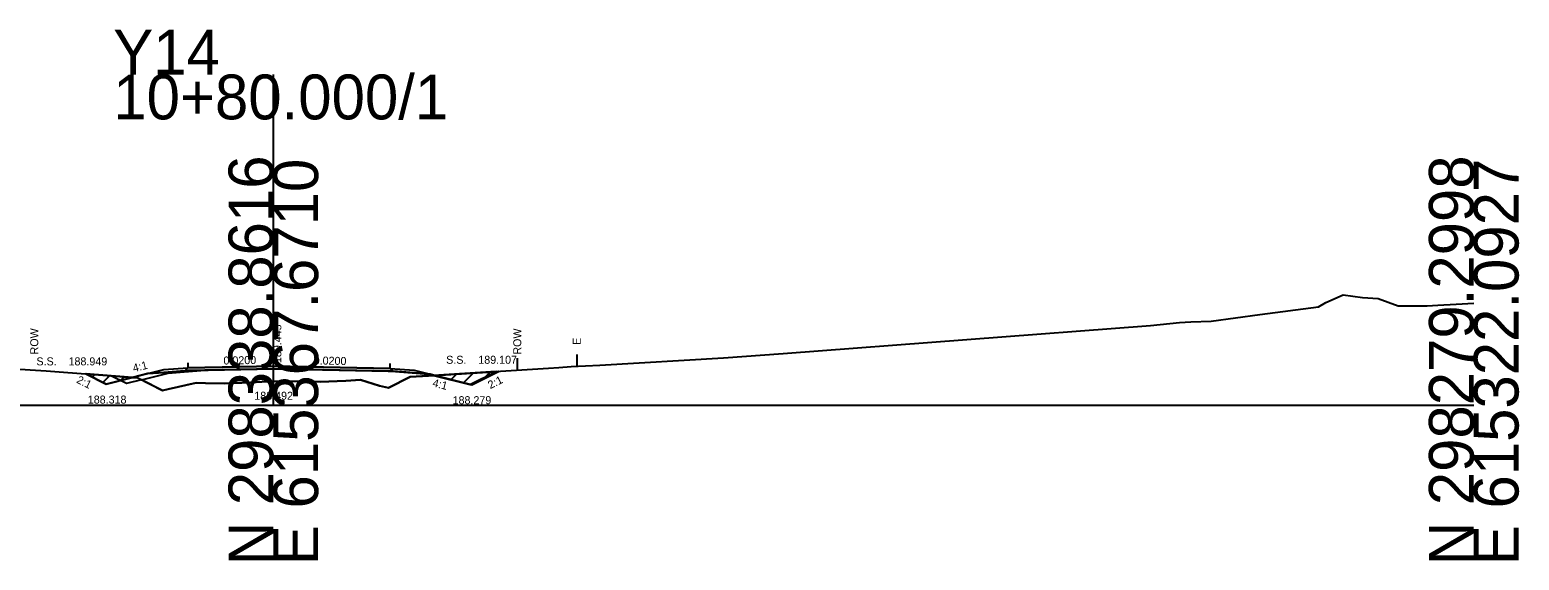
# Model space of a CAD drawing. Extents: x 517327 to 517505, y 114839 to 117370.
# Drawn here: x 517412.1 to 517505.2, y 116838.7 to 116871.8 of the extents above; entities that cross this region are included whole.
import ezdxf

# ---------------------------------------------------------------- set-up
doc = ezdxf.new("R2010")
doc.units = 0
for name, color, linetype in [('Exist XS Ground Line', 7, 'Continuous'), ('Old_Level_60', 7, 'Continuous'), ('Old_Level_63', 7, 'Continuous'), ('Prop XS Dump Level', 7, 'Continuous'), ('Prop XS Earthwork Shape', 7, 'Continuous'), ('Prop XS Elevation Labels', 7, 'Continuous'), ('Prop XS EOT Tick Mark', 7, 'Continuous'), ('Prop XS Exc Vertical Line 1', 7, 'Continuous'), ('Prop XS Exc Vertical Line 2', 7, 'Continuous'), ('Prop XS Finish Grade', 7, 'Continuous'), ('Prop XS Finish Grade Earthwork', 7, 'Continuous'), ('Prop XS Finish Grade Pavement', 7, 'Continuous'), ('Prop XS Hydro Elevations', 7, 'Continuous'), ('Prop XS Label Text', 7, 'Continuous'), ('Prop XS Pvmt Edge Slope', 7, 'Continuous'), ('Prop XS SE Text', 7, 'Continuous'), ('Prop XS Side Slope Text', 7, 'Continuous'), ('Prop XS Subgrade Earthwork', 7, 'Continuous'), ('Prop XS Suitable Common Exc Shape', 7, 'Continuous'), ('Scratch_Level_0', 7, 'Continuous')]:
    doc.layers.add(name, color=color, linetype=linetype)

msp = doc.modelspace()

# ---------------------------------------------------------------- linework, layer by layer
at = {"layer": 'Exist XS Ground Line'}
for p, q in [((517493.126, 116854.787), (517494.205, 116855.252)), ((517494.205, 116855.252), (517495.412, 116855.101)), ((517495.412, 116855.101), (517496.389, 116855.03)), ((517489.005, 116854.036), (517492.667, 116854.505)), ((517492.667, 116854.505), (517493.126, 116854.787)), ((517496.389, 116855.03), (517497.637, 116854.574)), ((517497.637, 116854.574), (517498.943, 116854.574)), ((517498.943, 116854.574), (517499.447, 116854.57)), ((517499.447, 116854.57), (517500.12, 116854.617)), ((517500.12, 116854.617), (517501.258, 116854.685)), ((517501.258, 116854.685), (517502.365, 116854.733)), ((517459.215, 116851.596), (517482.178, 116853.344)), ((517482.178, 116853.344), (517483.971, 116853.54)), ((517483.971, 116853.54), (517484.685, 116853.577)), ((517484.685, 116853.577), (517485.958, 116853.607)), ((517485.958, 116853.607), (517489.005, 116854.036)), ((517447.758, 116850.864), (517455.489, 116851.33)), ((517455.489, 116851.33), (517459.215, 116851.596)), ((517410.197, 116850.697), (517412.507, 116850.547)), ((517412.507, 116850.547), (517413.166, 116850.504)), ((517413.166, 116850.504), (517418.89, 116850.066)), ((517435.908, 116850.125), (517444.548, 116850.668)), ((517444.548, 116850.668), (517445.211, 116850.711)), ((517445.211, 116850.711), (517445.981, 116850.771)), ((517445.981, 116850.771), (517447.758, 116850.864)), ((517418.89, 116850.066), (517420.443, 116849.276)), ((517420.794, 116849.354), (517422.538, 116849.759)), ((517422.538, 116849.759), (517423.121, 116849.733)), ((517423.121, 116849.733), (517424.311, 116849.71)), ((517424.311, 116849.71), (517425.937, 116849.789)), ((517425.937, 116849.789), (517427.356, 116849.857)), ((517427.356, 116849.857), (517429.005, 116849.834)), ((517429.005, 116849.834), (517430.3, 116849.816)), ((517430.3, 116849.816), (517431.904, 116849.889)), ((517431.904, 116849.889), (517432.805, 116849.945)), ((517432.805, 116849.945), (517433.993, 116849.582)), ((517433.993, 116849.582), (517434.567, 116849.444)), ((517434.567, 116849.444), (517435.908, 116850.125)), ((517420.443, 116849.276), (517420.794, 116849.354))]:
    msp.add_line(p, q, dxfattribs=at)
at = {"layer": 'Old_Level_63'}
for p, q in [((517427.365, 116848.365), (517427.365, 116869.027)), ((517352.365, 116848.365), (517427.365, 116848.365)), ((517427.365, 116848.365), (517502.365, 116848.365))]:
    msp.add_line(p, q, dxfattribs=at)
at = {"layer": 'Prop XS Dump Level'}
for p, q in [((517422.019, 116850.703), (517427.365, 116850.81)), ((517427.365, 116850.81), (517434.67, 116850.664))]:
    msp.add_line(p, q, dxfattribs=at)
at = {"layer": 'Prop XS Earthwork Shape'}
for points in [[(517434.67, 116850.484), (517427.365, 116850.63), (517422.019, 116850.523), (517421.835, 116850.519), (517420.519, 116850.414), (517419.525, 116850.334), (517418.555, 116850.092), (517418.89, 116850.066), (517420.443, 116849.276), (517420.794, 116849.354), (517422.538, 116849.759), (517423.121, 116849.733), (517424.311, 116849.71), (517425.937, 116849.789), (517427.356, 116849.857), (517429.005, 116849.834), (517430.3, 116849.816), (517431.904, 116849.889), (517432.805, 116849.945), (517433.993, 116849.582), (517434.567, 116849.444), (517435.908, 116850.125), (517437.456, 116850.222), (517437.164, 116850.295), (517436.17, 116850.375), (517434.853, 116850.48)], [(517437.456, 116850.222), (517439.77, 116849.644), (517441.426, 116850.472)], [(517415.658, 116850.314), (517416.919, 116849.683), (517418.555, 116850.092)]]:
    msp.add_lwpolyline(points, close=True, dxfattribs=at)
at = {"layer": 'Prop XS EOT Tick Mark'}
for p, q in [((517422.019, 116851.008), (517422.019, 116850.703)), ((517434.67, 116850.664), (517434.67, 116850.969))]:
    msp.add_line(p, q, dxfattribs=at)
at = {"layer": 'Prop XS Exc Vertical Line 1'}
msp.add_line((517446.324, 116851.539), (517446.324, 116850.789), dxfattribs=at)
at = {"layer": 'Prop XS Exc Vertical Line 2'}
msp.add_line((517442.605, 116851.296), (517442.605, 116850.546), dxfattribs=at)
at = {"layer": 'Prop XS Finish Grade'}
for p, q in [((517419.525, 116850.334), (517420.519, 116850.583)), ((517420.519, 116850.583), (517422.019, 116850.703)), ((517434.67, 116850.664), (517436.17, 116850.544)), ((517436.17, 116850.544), (517437.164, 116850.295))]:
    msp.add_line(p, q, dxfattribs=at)
at = {"layer": 'Prop XS Finish Grade Earthwork'}
for p, q in [((517439.77, 116849.644), (517441.426, 116850.472)), ((517415.658, 116850.314), (517416.919, 116849.683)), ((517416.919, 116849.683), (517419.525, 116850.334)), ((517437.164, 116850.295), (517439.77, 116849.644))]:
    msp.add_line(p, q, dxfattribs=at)
at = {"layer": 'Prop XS Finish Grade Pavement'}
for p, q in [((517427.365, 116850.81), (517422.019, 116850.703)), ((517434.67, 116850.664), (517427.365, 116850.81))]:
    msp.add_line(p, q, dxfattribs=at)
at = {"layer": 'Prop XS Pvmt Edge Slope'}
for p, q in [((517421.835, 116850.519), (517422.019, 116850.703)), ((517434.67, 116850.664), (517434.853, 116850.48))]:
    msp.add_line(p, q, dxfattribs=at)
at = {"layer": 'Prop XS Subgrade Earthwork'}
for p, q in [((517419.525, 116850.334), (517420.519, 116850.414)), ((517420.519, 116850.414), (517421.835, 116850.519)), ((517421.835, 116850.519), (517422.019, 116850.523)), ((517427.365, 116850.63), (517422.019, 116850.523)), ((517434.67, 116850.484), (517427.365, 116850.63)), ((517434.67, 116850.484), (517434.853, 116850.48)), ((517434.853, 116850.48), (517436.17, 116850.375)), ((517436.17, 116850.375), (517437.164, 116850.295))]:
    msp.add_line(p, q, dxfattribs=at)
at = {"layer": 'Prop XS Suitable Common Exc Shape'}
for points in [[(517437.038, 116850.298), (517437.364, 116850.216), (517435.908, 116850.125), (517434.567, 116849.444), (517433.993, 116849.582), (517432.805, 116849.945), (517431.904, 116849.889), (517430.3, 116849.816), (517429.005, 116849.834), (517427.356, 116849.857), (517425.937, 116849.789), (517424.311, 116849.71), (517423.121, 116849.733), (517422.538, 116849.759), (517420.794, 116849.354), (517420.443, 116849.276), (517419.13, 116849.944), (517420.792, 116850.36), (517421.786, 116850.439), (517423.102, 116850.545), (517423.286, 116850.548), (517427.365, 116850.63), (517434.544, 116850.486), (517434.727, 116850.483), (517436.044, 116850.377)], [(517439.644, 116849.646), (517441.276, 116850.463), (517437.364, 116850.216)], [(517418.89, 116850.066), (517419.13, 116849.944), (517418.186, 116849.708), (517417.213, 116850.195)]]:
    msp.add_lwpolyline(points, close=True, dxfattribs=at)
at = {"layer": 'Scratch_Level_0'}
for p, q in [((517437.456, 116850.222), (517441.426, 116850.472)), ((517441.426, 116850.472), (517439.77, 116849.644)), ((517440.488, 116850.003), (517440.926, 116850.44)), ((517415.658, 116850.314), (517418.555, 116850.092)), ((517416.919, 116849.683), (517415.658, 116850.314)), ((517416.052, 116850.117), (517416.207, 116850.272)), ((517416.712, 116849.787), (517417.126, 116850.201)), ((517418.555, 116850.092), (517416.919, 116849.683)), ((517417.824, 116849.909), (517418.046, 116850.131)), ((517439.77, 116849.644), (517437.456, 116850.222)), ((517437.681, 116850.166), (517437.756, 116850.241)), ((517438.473, 116849.968), (517438.813, 116850.307)), ((517439.265, 116849.77), (517439.869, 116850.374))]:
    msp.add_line(p, q, dxfattribs=at)

# ---------------------------------------------------------------- texts
at = {"layer": 'Old_Level_60'}
msp.add_text('188.492', height=0.5, dxfattribs=at).set_placement((517426.174, 116848.701))
at = {"layer": 'Old_Level_63'}
for s, p in [('Y14', (517417.362, 116869.027)), ('10+80.000/1', (517417.365, 116866.227))]:
    msp.add_text(s, height=2.8, dxfattribs=at).set_placement(p)
for s, p in [('N 298338.8616', (517427.365, 116838.364)), ('E 615367.6710', (517430.165, 116838.365)), ('N 298279.2998', (517502.365, 116838.365)), ('E 615322.0927', (517505.165, 116838.365))]:
    msp.add_text(s, height=2.8, rotation=90, dxfattribs=at).set_placement(p)
at = {"layer": 'Prop XS Dump Level'}
for p in [(517420.519, 116850.571), (517436.17, 116850.532)]:
    msp.add_text('Case1', height=0.0122, dxfattribs=at).set_placement(p)
at = {"layer": 'Prop XS Elevation Labels'}
msp.add_text(' 189.445', height=0.5, rotation=90, dxfattribs=at).set_placement((517427.865, 116850.81))
at = {"layer": 'Prop XS Exc Vertical Line 1'}
msp.add_text('E', height=0.5, rotation=90, dxfattribs=at).set_placement((517446.574, 116852.132))
at = {"layer": 'Prop XS Exc Vertical Line 2'}
for p in [(517412.678, 116851.535), (517442.855, 116851.521)]:
    msp.add_text('ROW', height=0.5, rotation=90, dxfattribs=at).set_placement(p)
at = {"layer": 'Prop XS Hydro Elevations'}
for s, p in [('S.S.    188.949', (517412.563, 116850.849)), ('S.S.    189.107', (517438.164, 116850.951))]:
    msp.add_text(s, height=0.5, dxfattribs=at).set_placement(p)
at = {"layer": 'Prop XS Label Text'}
for rotation, p in [(14.03624, (517418.646, 116850.424)), (345.96376, (517437.272, 116849.537))]:
    msp.add_text('4:1', height=0.5, rotation=rotation, dxfattribs=at).set_placement(p)
at = {"layer": 'Prop XS SE Text'}
for rotation, p in [(1.14576, (517424.253, 116850.9)), (358.85423, (517429.882, 116850.912))]:
    msp.add_text('0.0200', height=0.5, rotation=rotation, dxfattribs=at).set_placement(p)
at = {"layer": 'Prop XS Side Slope Text'}
for rotation, p in [(333.43495, (517415.024, 116849.787)), (26.56505, (517440.922, 116849.363))]:
    msp.add_text('2:1', height=0.5, rotation=rotation, dxfattribs=at).set_placement(p)
for s, p in [('188.318', (517415.772, 116848.463)), ('188.279', (517438.565, 116848.424))]:
    msp.add_text(s, height=0.5, dxfattribs=at).set_placement(p)

doc.saveas('drawing.dxf')
